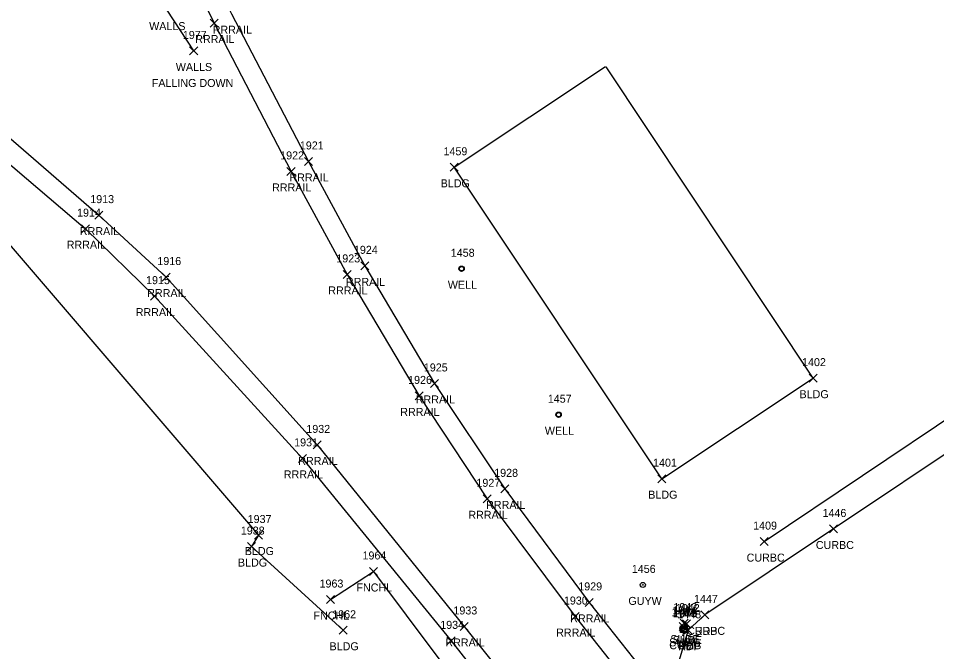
# Model space of a CAD drawing. Extents: x 1635588 to 1637550, y 621583 to 623638.
# Drawn here: x 1636661.5 to 1636890.8, y 622165 to 622323.2 of the extents above; entities that cross this region are included whole.
import ezdxf

# ---------------------------------------------------------------- set-up
doc = ezdxf.new("R2010")
doc.units = 0
for name, color, linetype in [('C_A', 7, 'Continuous'), ('C_I', 7, 'Continuous'), ('CBP', 7, 'Continuous'), ('L_A', 7, 'Continuous'), ('L_C', 7, 'Continuous'), ('L_I', 7, 'Continuous'), ('L_TIC', 7, 'Continuous'), ('LBC', 7, 'Continuous'), ('LFNC', 7, 'Continuous'), ('LWS', 7, 'Continuous'), ('M_A', 7, 'Continuous'), ('M_I', 7, 'Continuous'), ('MPIR', 7, 'Continuous'), ('P_A', 7, 'Continuous'), ('P_I', 7, 'Continuous'), ('P_TIC', 7, 'Continuous'), ('PET', 7, 'Continuous'), ('R_A', 7, 'Continuous'), ('R_I', 7, 'Continuous'), ('R_TIC', 7, 'Continuous'), ('RC', 7, 'Continuous'), ('RR', 7, 'Continuous'), ('U_A', 7, 'Continuous'), ('U_I', 7, 'Continuous'), ('U_TIC', 7, 'Continuous'), ('UP', 7, 'Continuous'), ('UPGW', 7, 'Continuous'), ('UWW', 7, 'Continuous')]:
    doc.layers.add(name, color=color, linetype=linetype)

msp = doc.modelspace()

# ---------------------------------------------------------------- linework, layer by layer
at = {"layer": 'CBP'}
for radius in [0.625, 0.0833]:
    msp.add_circle((1636827.81, 622170.58), radius, dxfattribs=at)
at = {"layer": 'L_TIC'}
for points in [[(1636704.24, 622314.08), (1636706.24, 622316.08)], [(1636706.24, 622314.08), (1636704.24, 622316.08)], [(1636769.34, 622285.02), (1636771.34, 622287.02)], [(1636771.34, 622285.02), (1636769.34, 622287.02)], [(1636858.96, 622232.34), (1636860.96, 622234.34)], [(1636860.96, 622232.34), (1636858.96, 622234.34)], [(1636821.18, 622207.23), (1636823.18, 622209.23)], [(1636823.18, 622207.23), (1636821.18, 622209.23)], [(1636821.18, 622207.23), (1636823.18, 622209.23)], [(1636823.18, 622207.23), (1636821.18, 622209.23)], [(1636720.42, 622193.15), (1636722.42, 622195.15)], [(1636722.42, 622193.15), (1636720.42, 622195.15)], [(1636718.71, 622190.27), (1636720.71, 622192.27)], [(1636720.71, 622190.27), (1636718.71, 622192.27)], [(1636749.15, 622184.05), (1636751.15, 622186.05)], [(1636751.15, 622184.05), (1636749.15, 622186.05)], [(1636738.42, 622177.03), (1636740.42, 622179.03)], [(1636740.42, 622177.03), (1636738.42, 622179.03)], [(1636741.59, 622169.36), (1636743.59, 622171.36)], [(1636743.59, 622169.36), (1636741.59, 622171.36)]]:
    msp.add_lwpolyline(points, dxfattribs=at)
at = {"layer": 'LBC'}
for points in [[(1636608.08, 622317.23), (1636635.72, 622294.09), (1636721.42, 622194.15), (1636719.71, 622191.27), (1636742.59, 622170.36)], [(1636822.18, 622208.23), (1636770.34, 622286.02), (1636808.08, 622311.18)], [(1636822.18, 622208.23), (1636859.96, 622233.34), (1636808.26, 622311.13)]]:
    msp.add_lwpolyline(points, dxfattribs=at)
at = {"layer": 'LFNC'}
msp.add_lwpolyline([(1636739.42, 622178.03), (1636750.15, 622185.05), (1636782.77, 622141.38), (1636766.09, 622126.73)], dxfattribs=at)
at = {"layer": 'LWS'}
msp.add_lwpolyline([(1636664.51, 622393.13), (1636677.7, 622366.16), (1636698.58, 622325.29), (1636705.24, 622315.08)], dxfattribs=at)
at = {"layer": 'MPIR'}
msp.add_lwpolyline([(1636827.34, 622171.19), (1636827.05, 622170.69), (1636827.63, 622170.69)], close=True, dxfattribs=at)
msp.add_circle((1636827.34, 622170.86), 0.667, dxfattribs=at)
at = {"layer": 'P_TIC'}
for points in [[(1636831.89, 622173.21), (1636833.89, 622175.21)], [(1636833.89, 622173.21), (1636831.89, 622175.21)], [(1636827.72, 622169.37), (1636829.72, 622171.37)], [(1636829.72, 622169.37), (1636827.72, 622171.37)]]:
    msp.add_lwpolyline(points, dxfattribs=at)
at = {"layer": 'PET'}
for points in [[(1636832.89, 622174.21), (1636828.72, 622170.37)], [(1636828.72, 622170.37), (1636825.41, 622159.33)]]:
    msp.add_lwpolyline(points, dxfattribs=at)
at = {"layer": 'R_TIC'}
for points in [[(1636709.33, 622321.06), (1636711.33, 622323.06)], [(1636711.33, 622321.06), (1636709.33, 622323.06)], [(1636732.88, 622286.48), (1636734.88, 622288.48)], [(1636734.88, 622286.48), (1636732.88, 622288.48)], [(1636728.55, 622283.99), (1636730.55, 622285.99)], [(1636730.55, 622283.99), (1636728.55, 622285.99)], [(1636680.53, 622273.07), (1636682.53, 622275.07)], [(1636682.53, 622273.07), (1636680.53, 622275.07)], [(1636677.25, 622269.68), (1636679.25, 622271.68)], [(1636679.25, 622269.68), (1636677.25, 622271.68)], [(1636746.97, 622260.4), (1636748.97, 622262.4)], [(1636748.97, 622260.4), (1636746.97, 622262.4)], [(1636742.57, 622258.26), (1636744.57, 622260.26)], [(1636744.57, 622258.26), (1636742.57, 622260.26)], [(1636697.35, 622257.6), (1636699.35, 622259.6)], [(1636699.35, 622257.6), (1636697.35, 622259.6)], [(1636694.49, 622252.83), (1636696.49, 622254.83)], [(1636696.49, 622252.83), (1636694.49, 622254.83)], [(1636764.42, 622231.02), (1636766.42, 622233.02)], [(1636766.42, 622231.02), (1636764.42, 622233.02)], [(1636760.55, 622227.91), (1636762.55, 622229.91)], [(1636762.55, 622227.91), (1636760.55, 622229.91)], [(1636735.07, 622215.66), (1636737.07, 622217.66)], [(1636737.07, 622215.66), (1636735.07, 622217.66)], [(1636731.46, 622212.3), (1636733.46, 622214.3)], [(1636733.46, 622212.3), (1636731.46, 622214.3)], [(1636781.99, 622204.69), (1636783.99, 622206.69)], [(1636783.99, 622204.69), (1636781.99, 622206.69)], [(1636777.55, 622202.2), (1636779.55, 622204.2)], [(1636779.55, 622202.2), (1636777.55, 622204.2)], [(1636864.05, 622194.66), (1636866.05, 622196.66)], [(1636866.05, 622194.66), (1636864.05, 622196.66)], [(1636846.75, 622191.51), (1636848.75, 622193.51)], [(1636848.75, 622191.51), (1636846.75, 622193.51)], [(1636803, 622176.32), (1636805, 622178.32)], [(1636805, 622176.32), (1636803, 622178.32)], [(1636799.49, 622172.78), (1636801.49, 622174.78)], [(1636801.49, 622172.78), (1636799.49, 622174.78)], [(1636831.89, 622173.21), (1636833.89, 622175.21)], [(1636833.89, 622173.21), (1636831.89, 622175.21)], [(1636771.81, 622170.31), (1636773.81, 622172.31)], [(1636773.81, 622170.31), (1636771.81, 622172.31)], [(1636768.51, 622166.71), (1636770.51, 622168.71)], [(1636770.51, 622166.71), (1636768.51, 622168.71)]]:
    msp.add_lwpolyline(points, dxfattribs=at)
at = {"layer": 'RC'}
msp.add_lwpolyline([(1636847.75, 622192.51), (1636896.86, 622225.51), (1636898.66, 622226.04), (1636899.64, 622225.8), (1636900.46, 622224.94), (1636901.02, 622223.87), (1636901.26, 622222.1), (1636900.98, 622220.55), (1636899.93, 622219.05), (1636865.05, 622195.66), (1636832.89, 622174.21)], dxfattribs=at)
at = {"layer": 'RR'}
for points in [[(1636590.62, 622643.06), (1636603.96, 622594.72), (1636620.27, 622536.36), (1636632.07, 622498.45), (1636643.29, 622466.78), (1636655.39, 622436.56), (1636668.93, 622406.09), (1636689.56, 622363.97), (1636710.33, 622322.06), (1636729.55, 622284.99), (1636743.57, 622259.26), (1636761.55, 622228.91), (1636778.55, 622203.2), (1636800.49, 622173.78), (1636817.8, 622151.9), (1636836.04, 622130.9), (1636862.72, 622101.67), (1636929.58, 622028.72), (1636988.41, 621964.46), (1637027.08, 621922.66), (1637047.82, 621899.75)], [(1636595.36, 622644.51), (1636608.64, 622596.11), (1636625.13, 622537.69), (1636636.8, 622500.24), (1636648.02, 622468.59), (1636659.97, 622438.55), (1636673.52, 622408.34), (1636693.85, 622366.08), (1636714.7, 622324.39), (1636733.88, 622287.48), (1636747.97, 622261.4), (1636765.42, 622232.02), (1636782.99, 622205.69), (1636804, 622177.32), (1636821.45, 622155.32), (1636839.4, 622134.64), (1636866.41, 622104.91), (1636933.01, 622032.15), (1636992.12, 621967.88), (1637026.25, 621930.62), (1637051.37, 621903.17)], [(1636647.57, 622303.46), (1636681.53, 622274.07), (1636698.35, 622258.6), (1636736.07, 622216.66), (1636772.81, 622171.31), (1636793.48, 622145.5), (1636799.12, 622138.4), (1636815.41, 622118.42), (1636845.94, 622085.12), (1636908.55, 622026.21), (1636983.07, 621959.74), (1637027.08, 621922.66), (1637050.39, 621902.14), (1637074.4, 621880.01)], [(1636645.23, 622298.69), (1636678.25, 622270.68), (1636695.49, 622253.83), (1636732.46, 622213.3), (1636769.51, 622167.71), (1636788.83, 622143.09), (1636795.06, 622135.55), (1636811.52, 622115.54), (1636841.96, 622081.95), (1636905.16, 622022.78), (1636979.87, 621956.02), (1637024.02, 621918.73), (1637048, 621897.73), (1637071.19, 621876.23)]]:
    msp.add_lwpolyline(points, dxfattribs=at)
at = {"layer": 'U_TIC'}
for points in [[(1636826.75, 622171.15), (1636828.75, 622173.15)], [(1636828.75, 622171.15), (1636826.75, 622173.15)], [(1636827.35, 622170.93), (1636829.35, 622172.93)], [(1636829.35, 622170.93), (1636827.35, 622172.93)], [(1636826.51, 622170.34), (1636828.51, 622172.34)], [(1636828.51, 622170.34), (1636826.51, 622172.34)]]:
    msp.add_lwpolyline(points, dxfattribs=at)
at = {"layer": 'UP'}
for p, q in [((1636826.8, 622169.79), (1636826.8, 622171.46)), ((1636826.8, 622171.46), (1636828.47, 622171.46)), ((1636827.88, 622172.29), (1636827.63, 622171.46)), ((1636827.63, 622170.62), (1636827.63, 622170.62)), ((1636828.47, 622171.46), (1636828.47, 622169.79)), ((1636828.47, 622169.79), (1636826.8, 622169.79)), ((1636827.38, 622168.96), (1636827.63, 622169.79))]:
    msp.add_line(p, q, dxfattribs=at)
msp.add_circle((1636827.63, 622170.62), 0.833, dxfattribs=at)
at = {"layer": 'UPGW'}
for radius in [0.625, 0.0833]:
    msp.add_circle((1636817.42, 622181.69), radius, dxfattribs=at)
at = {"layer": 'UWW'}
for centre, radius in [((1636772.15, 622260.67), 0.667), ((1636772.15, 622260.67), 0.625), ((1636772.15, 622260.67), 0.583), ((1636772.15, 622260.67), 0.542), ((1636796.39, 622224.21), 0.667), ((1636796.39, 622224.21), 0.625), ((1636796.39, 622224.21), 0.583), ((1636796.39, 622224.21), 0.542)]:
    msp.add_circle(centre, radius, dxfattribs=at)

# ---------------------------------------------------------------- texts
at = {"layer": 'C_A'}
msp.add_text('TIE', height=2, dxfattribs=at).set_placement((1636825.89, 622165.58))
at = {"layer": 'C_I'}
msp.add_text('1970', height=2, dxfattribs=at).set_placement((1636825.03, 622173.58))
at = {"layer": 'L_A'}
for s, p in [('WALLS', (1636694.12, 622320.29)), ('WALLS', (1636700.78, 622310.08)), ('BLDG', (1636766.93, 622281.02)), ('BLDG', (1636856.55, 622228.34)), ('BLDG', (1636818.77, 622203.23)), ('BLDG', (1636818.77, 622203.23)), ('BLDG', (1636718.01, 622189.15)), ('BLDG', (1636716.3, 622186.27)), ('FNCHL', (1636745.9, 622180.05)), ('FNCHL', (1636735.17, 622173.03)), ('BLDG', (1636739.18, 622165.36))]:
    msp.add_text(s, height=2, dxfattribs=at).set_placement(p)
at = {"layer": 'L_C'}
msp.add_text('FALLING DOWN', height=2, dxfattribs=at).set_placement((1636694.79, 622306.08))
at = {"layer": 'L_I'}
for s, p in [('1977', (1636702.54, 622318.08)), ('1459', (1636767.64, 622289.02)), ('1402', (1636857.19, 622236.34)), ('1401', (1636819.98, 622211.23)), ('1401', (1636819.98, 622211.23)), ('1937', (1636718.73, 622197.15)), ('1938', (1636717.02, 622194.27)), ('1964', (1636747.41, 622188.05)), ('1963', (1636736.68, 622181.03)), ('1962', (1636739.85, 622173.36))]:
    msp.add_text(s, height=2, dxfattribs=at).set_placement(p)
at = {"layer": 'M_A'}
msp.add_text('IP', height=2, dxfattribs=at).set_placement((1636826.39, 622165.86))
at = {"layer": 'M_I'}
msp.add_text('1464', height=2, dxfattribs=at).set_placement((1636824.6, 622173.86))
at = {"layer": 'P_A'}
for p in [(1636830.38, 622169.21), (1636826.21, 622165.37)]:
    msp.add_text('RDP', height=2, dxfattribs=at).set_placement(p)
at = {"layer": 'P_I'}
for s, p in [('1447', (1636830.2, 622177.21)), ('1448', (1636826.03, 622173.37))]:
    msp.add_text(s, height=2, dxfattribs=at).set_placement(p)
at = {"layer": 'R_A'}
for s, p in [('RRRAIL', (1636709.99, 622319.39)), ('RRRAIL', (1636705.63, 622317.06)), ('RRRAIL', (1636729.17, 622282.48)), ('RRRAIL', (1636724.84, 622279.99)), ('RRRAIL', (1636676.82, 622269.07)), ('RRRAIL', (1636673.54, 622265.68)), ('RRRAIL', (1636743.26, 622256.4)), ('RRRAIL', (1636693.64, 622253.6)), ('RRRAIL', (1636738.86, 622254.26)), ('RRRAIL', (1636690.78, 622248.83)), ('RRRAIL', (1636760.72, 622227.02)), ('RRRAIL', (1636756.84, 622223.91)), ('RRRAIL', (1636731.36, 622211.66)), ('RRRAIL', (1636727.76, 622208.3)), ('RRRAIL', (1636778.29, 622200.69)), ('RRRAIL', (1636773.84, 622198.2)), ('CURBC', (1636860.63, 622190.66)), ('CURBC', (1636843.34, 622187.51)), ('RRRAIL', (1636799.29, 622172.32)), ('RRRAIL', (1636795.78, 622168.78)), ('CURBC', (1636828.47, 622169.21)), ('RRRAIL', (1636768.11, 622166.31))]:
    msp.add_text(s, height=2, dxfattribs=at).set_placement(p)
at = {"layer": 'R_I'}
for s, p in [('1921', (1636731.76, 622290.48)), ('1922', (1636726.85, 622287.99)), ('1913', (1636679.41, 622277.07)), ('1914', (1636676.12, 622273.68)), ('1923', (1636740.87, 622262.26)), ('1924', (1636745.27, 622264.4)), ('1916', (1636696.17, 622261.6)), ('1915', (1636693.36, 622256.83)), ('1925', (1636762.73, 622235.02)), ('1926', (1636758.8, 622231.91)), ('1932', (1636733.38, 622219.66)), ('1931', (1636730.34, 622216.3)), ('1928', (1636780.3, 622208.69)), ('1927', (1636775.86, 622206.2)), ('1446', (1636862.3, 622198.66)), ('1409', (1636844.97, 622195.51)), ('1929', (1636801.3, 622180.32)), ('1930', (1636797.71, 622176.78)), ('1447', (1636830.2, 622177.21)), ('1933', (1636770.12, 622174.31)), ('1934', (1636766.82, 622170.71))]:
    msp.add_text(s, height=2, dxfattribs=at).set_placement(p)
at = {"layer": 'U_A'}
for s, p in [('WELL', (1636768.72, 622255.67)), ('WELL', (1636792.95, 622219.21)), ('GUYW', (1636813.81, 622176.69)), ('SUBT', (1636824, 622166.34)), ('SUBE', (1636824.29, 622167.15)), ('SUBE', (1636824.89, 622166.93)), ('COMB', (1636824.02, 622165.62))]:
    msp.add_text(s, height=2, dxfattribs=at).set_placement(p)
at = {"layer": 'U_I'}
for s, p in [('1458', (1636769.46, 622263.67)), ('1457', (1636793.69, 622227.21)), ('1456', (1636814.67, 622184.69)), ('1943', (1636825.06, 622175.15)), ('1944', (1636824.81, 622174.34)), ('1945', (1636824.94, 622173.62)), ('1942', (1636825.66, 622174.93))]:
    msp.add_text(s, height=2, dxfattribs=at).set_placement(p)

doc.saveas('drawing.dxf')
